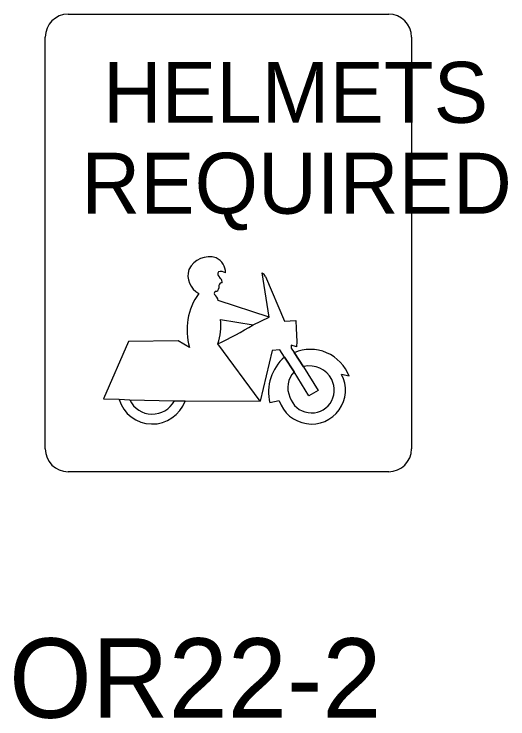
# Model space of a CAD drawing. Extents: x 42133 to 45533, y 41351 to 47951.
# Drawn here: x 42961.5 to 43008, y 44353.2 to 44419.7 of the extents above; entities that cross this region are included whole.
import ezdxf

# ---------------------------------------------------------------- set-up
doc = ezdxf.new("R2010")
doc.units = 0
doc.layers.add('P_TRAF_SIGN_SignDetails', color=7, linetype='Continuous')

msp = doc.modelspace()

# ---------------------------------------------------------------- linework, layer by layer
at = {"layer": 'P_TRAF_SIGN_SignDetails'}
for p, q in [((42966.58, 44419.718), (42996.804, 44419.718)), ((42964.426, 44378.707), (42964.426, 44417.545)), ((42998.957, 44417.545), (42998.957, 44378.707)), ((42985.545, 44391.118), (42984.875, 44395.293)), ((42985.196, 44394.972), (42986.971, 44390.74)), ((42985.545, 44391.118), (42980.728, 44392.686)), ((42980.945, 44390.91), (42984.025, 44390.4)), ((42984.025, 44390.4), (42985.545, 44391.118)), ((42984.034, 44390.4), (42985.545, 44391.118)), ((42986.971, 44390.74), (42988.058, 44390.797)), ((42988.058, 44390.797), (42988.095, 44390.06)), ((42988.095, 44390.06), (42988.152, 44388.832)), ((42972.275, 44388.814), (42969.914, 44383.43)), ((42976.969, 44388.889), (42972.275, 44388.814)), ((42978.027, 44388.266), (42976.969, 44388.889)), ((42984.686, 44383.184), (42980.681, 44388.606)), ((42984.686, 44383.184), (42980.681, 44388.606)), ((42987.614, 44388.492), (42987.595, 44388.209)), ((42988.114, 44388.322), (42987.614, 44388.492)), ((42988.152, 44388.832), (42988.114, 44388.322)), ((42985.81, 44387.982), (42984.686, 44383.184)), ((42986.546, 44388.039), (42985.81, 44387.982)), ((42986.971, 44387.359), (42986.546, 44388.039)), ((42987.595, 44388.209), (42987.888, 44387.775)), ((42987.888, 44387.775), (42988.785, 44386.452)), ((42988.785, 44386.452), (42987.888, 44387.775)), ((42987.897, 44385.961), (42986.971, 44387.359)), ((42986.971, 44387.359), (42987.897, 44385.961)), ((42988.785, 44386.452), (42990.154, 44384.204)), ((42989.267, 44383.694), (42987.897, 44385.961)), ((42993.082, 44385.546), (42992.355, 44385.716)), ((42990.154, 44384.204), (42989.267, 44383.694)), ((42969.914, 44383.43), (42971.378, 44383.373)), ((42971.378, 44383.373), (42972.388, 44383.317)), ((42971.378, 44383.373), (42972.388, 44383.317)), ((42972.379, 44383.335), (42976.572, 44383.241)), ((42976.572, 44383.241), (42977.611, 44383.222)), ((42976.591, 44383.222), (42977.602, 44383.203)), ((42977.611, 44383.222), (42984.686, 44383.184)), ((42986.49, 44383.241), (42985.592, 44383.033)), ((42996.804, 44376.535), (42966.58, 44376.535))]:
    msp.add_line(p, q, dxfattribs=at)
for centre, radius, start, end in [((42966.58, 44417.554), 2.159, 90, 180), ((42996.8, 44417.554), 2.159, 0, 90), ((42979.877, 44394.696), 2.122, 71.91415, 154.24277), ((42979.913, 44395.344), 1.504, 358.05659, 65.54626), ((42979.772, 44395.048), 1.894, 162.48021, 242.33171), ((42981.033, 44395.202), 0.339, 145.54678, 230.04869), ((42980.99, 44394.717), 0.717, 53.47107, 109.26082), ((42979.81, 44393.894), 1.448, 28.31307, 46.4254), ((42983.106, 44393.2), 2.746, 40.2393, 49.7607), ((42981.242, 44393.991), 0.469, 134.60417, 194.32873), ((42981.036, 44394.158), 0.208, 70.45401, 126.51797), ((42980.422, 44394.402), 0.685, 355.92187, 14.99324), ((42980.64, 44393.345), 0.283, 123.37537, 196.82504), ((42980.519, 44393.848), 0.27, 262.52898, 5.53833), ((42983.723, 44389.92), 5.933, 144.51214, 196.10644), ((42979.922, 44392.588), 0.809, 6.60734, 56.48097), ((42976.087, 44390.314), 4.899, 339.69178, 6.89273), ((42966.761, 44418.568), 33.038, 294.91566, 301.51253), ((42989.416, 44384.163), 3.915, 20.64547, 113.06461), ((42989.847, 44384.051), 4.377, 131.00209, 193.33662), ((42989.357, 44384.221), 2.305, 26.04696, 104.27207), ((42989.529, 44384.235), 3.195, 198.09167, 27.74776), ((42989.438, 44384.466), 2.146, 135.98765, 204.72968), ((42989.529, 44384.235), 2.145, 198.09167, 27.74776), ((42974.518, 44384.33), 3.286, 197.12766, 340.09346), ((42974.518, 44384.33), 2.354, 205.44767, 332.08002), ((42966.58, 44378.7), 2.159, 180, 270), ((42996.8, 44378.7), 2.159, 270, 0)]:
    msp.add_arc(centre, radius, start, end, dxfattribs=at)

# ---------------------------------------------------------------- texts
for s, height, p in [('HELMETS', 5.7503, (42969.858, 44409.46)), ('REQUIRED', 5.7503, (42967.823, 44400.884)), ('OR22-2', 7.5, (42961.01, 44353.326))]:
    msp.add_text(s, height=height, dxfattribs=at).set_placement(p)

doc.saveas('drawing.dxf')
